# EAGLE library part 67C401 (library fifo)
FIFO
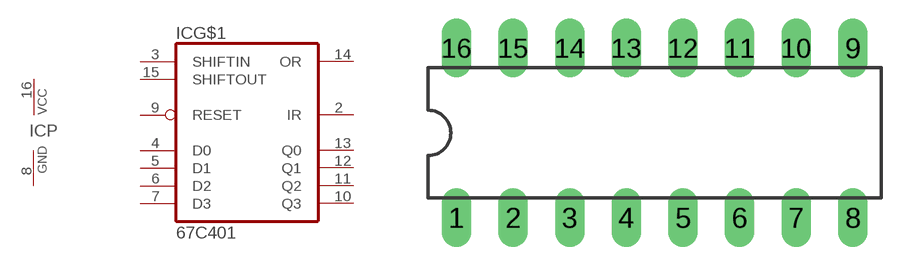
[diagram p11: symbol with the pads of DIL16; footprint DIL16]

Designator prefix IC; gates G$1=67C401 P=PWRN

## 67C401 (OC_FARNELL: unknown; OC_NEWARK: unknown)  [DIL16]
2  G$1:IR  out
3  G$1:SHIFTIN  in
4  G$1:D0  in
5  G$1:D1  in
6  G$1:D2  in
7  G$1:D3  in
8  P:GND  pwr
9  G$1:RESET  in
10  G$1:Q3  out
11  G$1:Q2  out
12  G$1:Q1  out
13  G$1:Q0  out
14  G$1:OR  out
15  G$1:SHIFTOUT  in
16  P:VCC  pwr

## Footprint DIL16 (pad centres in mm)
Dual In Line Package
drill 0.813 long: 1 -8.89,-3.81; 2 -6.35,-3.81; 3 -3.81,-3.81; 4 -1.27,-3.81; 5 1.27,-3.81; 6 3.81,-3.81; 7 6.35,-3.81; 8 8.89,-3.81; 9 8.89,3.81; 10 6.35,3.81; 11 3.81,3.81; 12 1.27,3.81; 13 -1.27,3.81; 14 -3.81,3.81; 15 -6.35,3.81; 16 -8.89,3.81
